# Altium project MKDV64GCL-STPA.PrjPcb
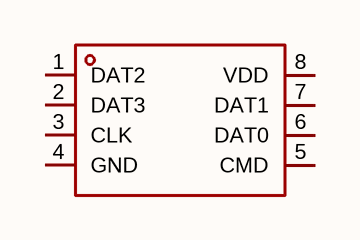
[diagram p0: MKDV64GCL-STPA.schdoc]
1 sheet, 1 parts. Net scope: global (net labels, ports and power ports of the same name join across sheets).

## Sheet MKDV64GCL-STPA.schdoc
size 127 x 101 mm

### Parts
U?  mkdv64gcl-stpa  [LGA-8_L8.0-W6.6-P1.27-TL-MKDV32GIL-STPB]  (value not drawn)

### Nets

Not connected (* = marked no-connect by the designer): U? 1(DAT2) 2(DAT3) 3(CLK) 4(GND) 5(CMD) 6(DAT0) 7(DAT1) 8(VDD)

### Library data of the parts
U? = mkdv64gcl-stpa: 存储容量:64Gbit;时钟频率(fc):50MHz;工作电压:3.3V;; Manufacturer: MK(米客方德); AddInBom: yes; Memory Size: 64Gbit; Interface: SPI; Clock Frequency: 50MHz; Voltage - Supply: 3.3V; Standby Supply Current: 190uA; Program / Erase Cycles: 5千次; ECC: 有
